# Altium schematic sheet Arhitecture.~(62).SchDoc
size A3; SheetNumber: 1; SheetTotal: 14
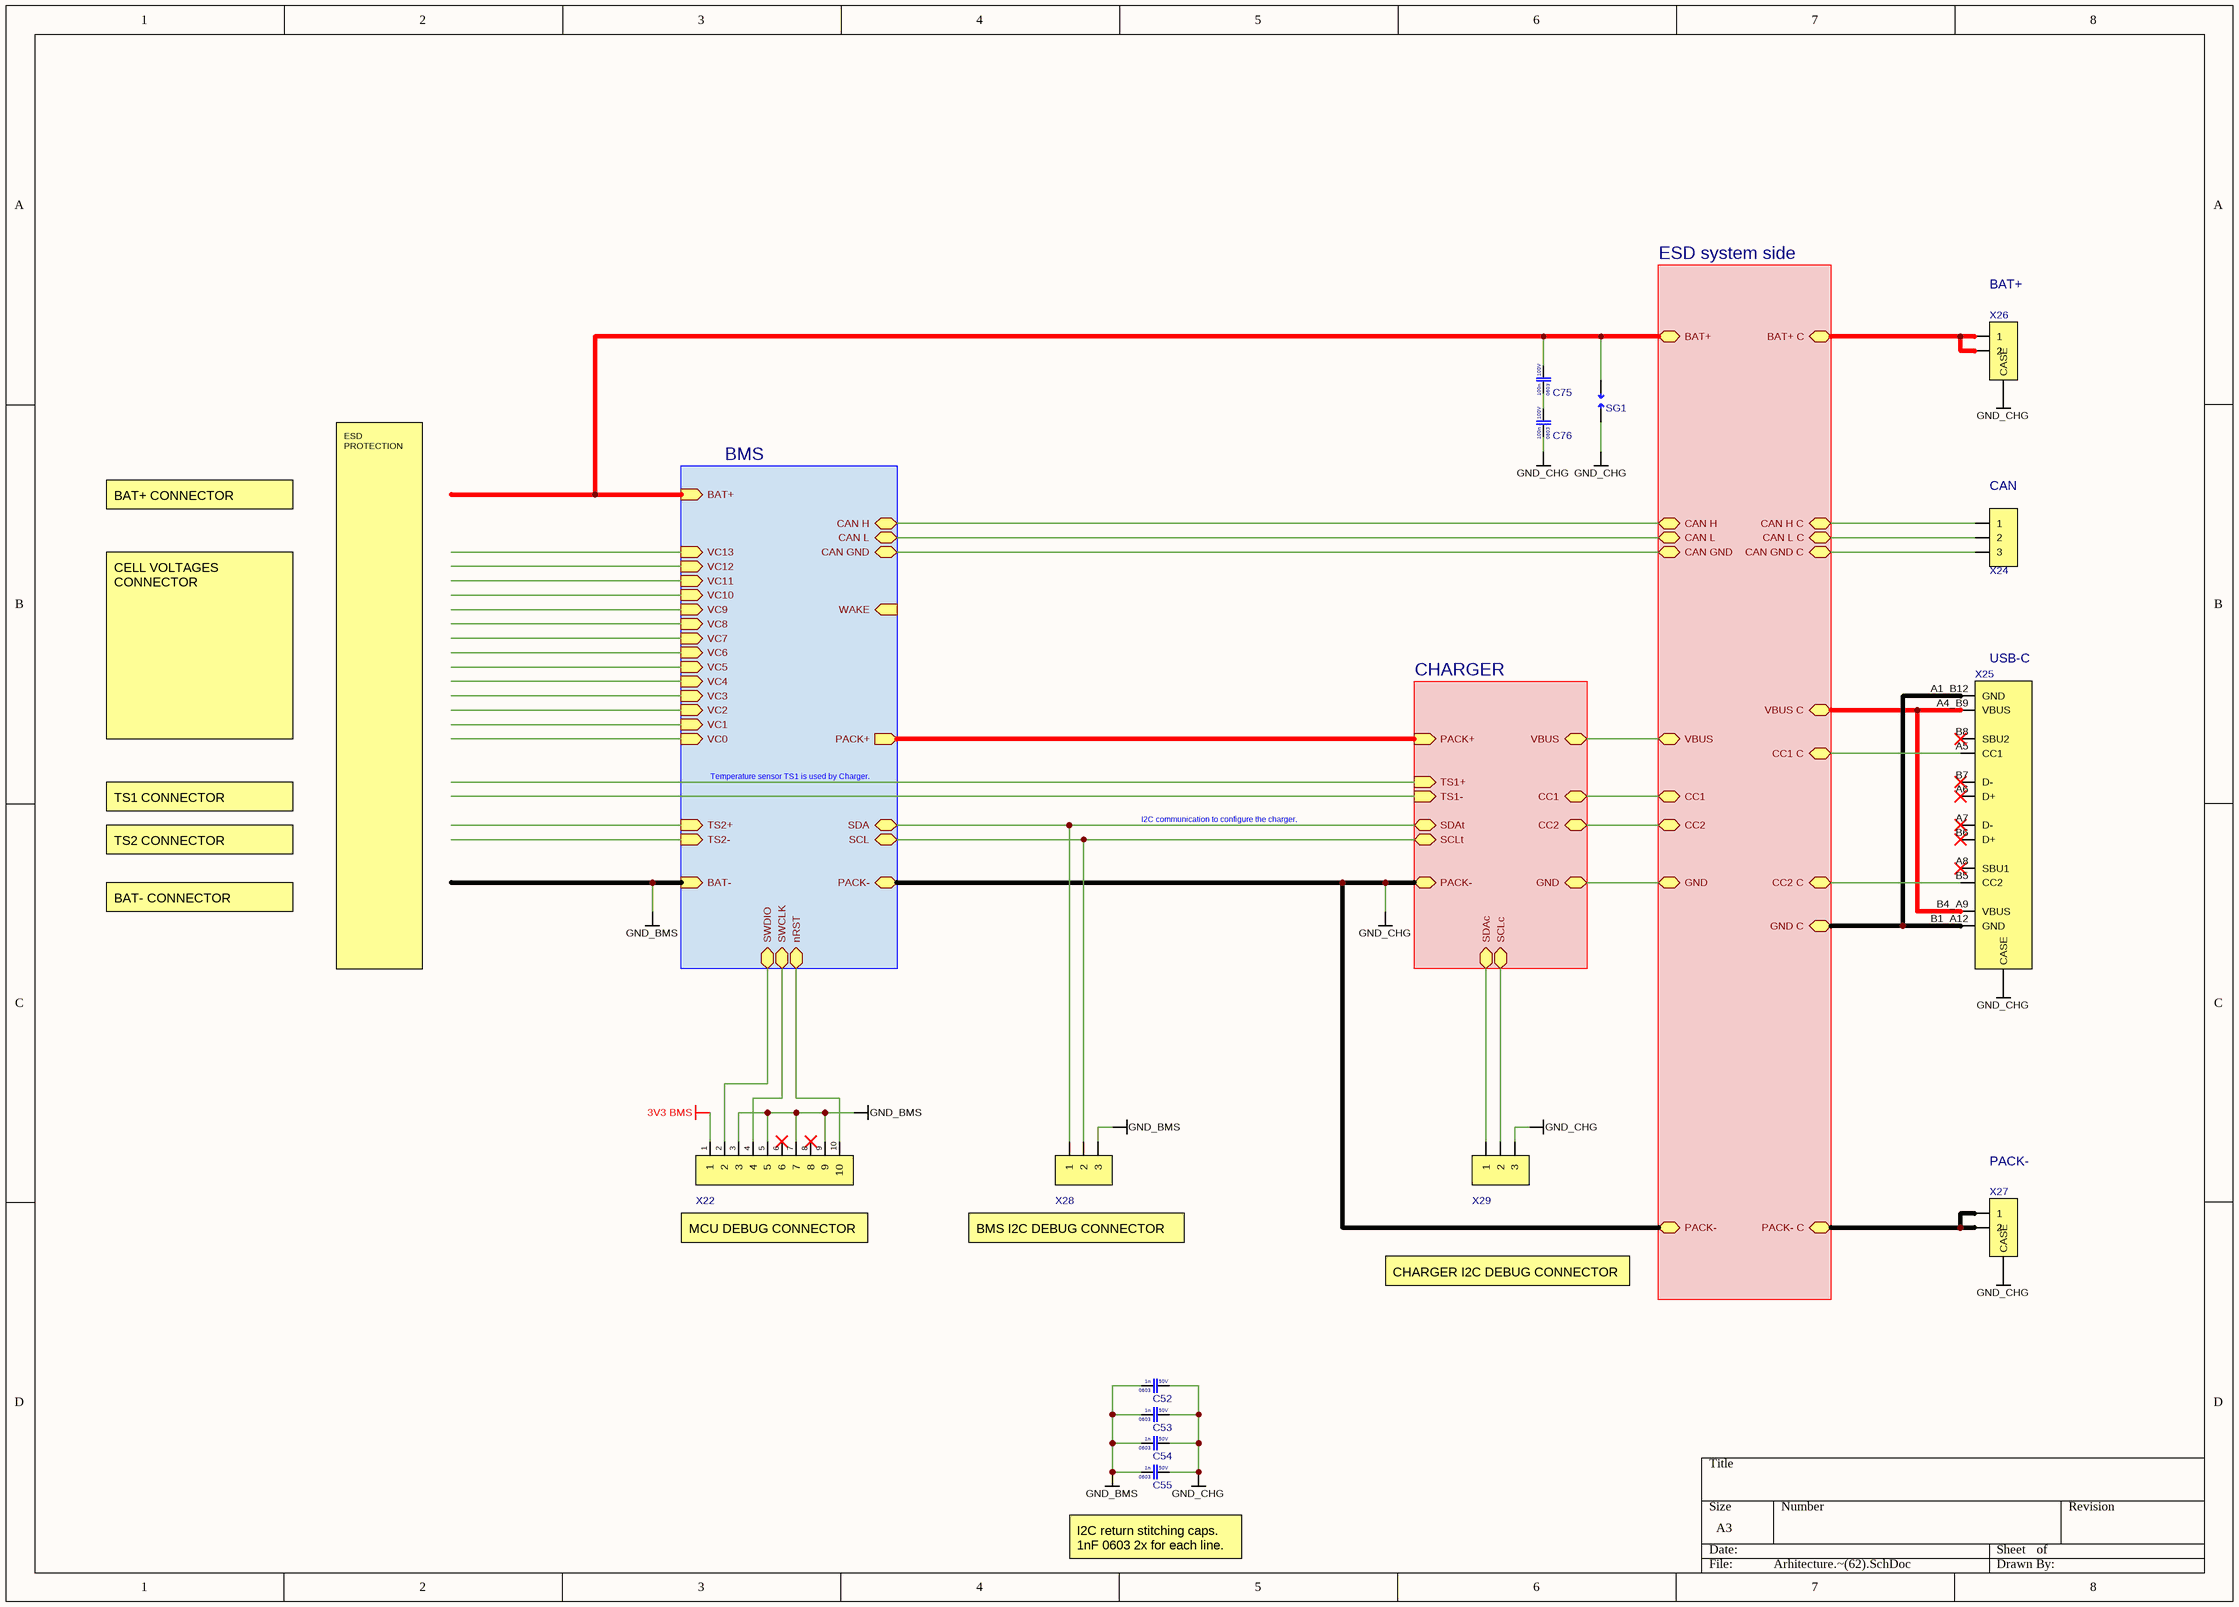
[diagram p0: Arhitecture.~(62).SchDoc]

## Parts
C52  Voltage Rating: 50V  Case Code (Imperial): 0603  Capacitance: 1n  [CAP 0603]  (hidden comment: CL10B102KB8NNNC)
C53  Voltage Rating: 50V  Case Code (Imperial): 0603  Capacitance: 1n  [CAP 0603]  (hidden comment: CL10B102KB8NNNC)
C54  Voltage Rating: 50V  Case Code (Imperial): 0603  Capacitance: 1n  [CAP 0603]  (hidden comment: CL10B102KB8NNNC)
C55  Voltage Rating: 50V  Case Code (Imperial): 0603  Capacitance: 1n  [CAP 0603]  (hidden comment: CL10B102KB8NNNC)
C75  Voltage Rating: 100V  Case Code (Imperial): 0603  Capacitance: 100n  [CAP 0603]  (hidden comment: CC0603KRX7R0BB104)
C76  Voltage Rating: 100V  Case Code (Imperial): 0603  Capacitance: 100n  [CAP 0603]  (hidden comment: CC0603KRX7R0BB104)
SG1  Spark gap  [Spark Gap 0.270mm]  (value not drawn)  (no BOM)
X22  HX IDC127-2-05-S-4.9  [JTAG Cortex connector]  (value not drawn)
X24  S3B-XH-A-1(LF)(SN)  [S3B-XH-A-1(LF)(SN)]  (value not drawn)
X25  USB-TYPE-C-018  [TYPE-C 16PIN 2MD]  (value not drawn)
X26  XT30PW-M30.G.Y  [XT30PW-M30.G.Y]  (value not drawn)
X27  XT30PW-M30.G.Y  [XT30PW-M30.G.Y]  (value not drawn)
X28  2.54-1*3PPin  [Pin header 1x3 2.54mmP THT Vertical]  (value not drawn)
X29  2.54-1*3PPin  [Pin header 1x3 2.54mmP THT Vertical]  (value not drawn)

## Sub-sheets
BMS = BMS.SchDoc: BAT+ (in), BAT- (in), VC0 (in), VC1 (in), VC2 (in), VC3 (in), VC4 (in), VC5 (in), VC6 (in), VC7 (in), VC8 (in), VC9 (in), VC10 (in), VC11 (in), VC12 (in), VC13 (in), PACK+ (out), PACK- (bidir), SCL (bidir), SDA (bidir), CAN H (bidir), CAN L (bidir), TS2+ (in), TS2- (in), WAKE (in), SWDIO (bidir), SWCLK (bidir), nRST (bidir), CAN GND (bidir)
CHARGER = CHARGER.SchDoc: PACK+ (in), PACK- (bidir), SDAt (bidir), SCLt (bidir), TS1+ (in), TS1- (in), SDAc (bidir), SCLc (bidir), CC1 (bidir), CC2 (bidir), GND (bidir), VBUS (bidir)
ESD system side = ESD system side.SchDoc: CAN H (bidir), CAN L (bidir), CAN GND (bidir), CAN H C (bidir), CAN L C (bidir), CAN GND C (bidir), VBUS C (bidir), GND C (bidir), CC1 C (bidir), CC2 C (bidir), VBUS (bidir), CC1 (bidir), CC2 (bidir), GND (bidir), BAT+ C (bidir), BAT+ (bidir), PACK- C (bidir), PACK- (bidir)

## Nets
3V3 BMS: X22.1
GND_BMS: C52.1 C53.1 C54.1 C55.1 X22.3 X22.5 X22.7 X22.9 X28.3 ; sheet BMS/BAT-
GND_CHG: C52.2 C53.2 C54.2 C55.2 C76.1 SG1.1 X25.CASE X26.CASE X27.CASE X29.3 ; sheet BMS/PACK-, sheet CHARGER/PACK-, sheet ESD system side/PACK-
NetC75_1: C75.1 C76.2
NetC75_2: C75.2 SG1.2 ; sheet BMS/BAT+, sheet ESD system side/BAT+
NetX22_2: X22.2 ; sheet BMS/SWDIO
NetX22_4: X22.4 ; sheet BMS/SWCLK
NetX22_10: X22.10 ; sheet BMS/nRST
NetX24_1: X24.1 ; sheet ESD system side/CAN H C
NetX24_2: X24.2 ; sheet ESD system side/CAN L C
NetX24_3: X24.3 ; sheet ESD system side/CAN GND C
NetX25_A1_B12: X25.A1_B12(GND) X25.B1_A12(GND) ; sheet ESD system side/GND C
NetX25_A4_B9: X25.A4_B9(VBUS) X25.B4_A9(VBUS) ; sheet ESD system side/VBUS C
NetX25_A5: X25.A5(CC1) ; sheet ESD system side/CC1 C
NetX25_B5: X25.B5(CC2) ; sheet ESD system side/CC2 C
NetX26_1: X26.1 X26.2 ; sheet ESD system side/BAT+ C
NetX27_1: X27.1 X27.2 ; sheet ESD system side/PACK- C
NetX28_1: X28.1 ; sheet BMS/SDA, sheet CHARGER/SDAt
NetX28_2: X28.2 ; sheet BMS/SCL, sheet CHARGER/SCLt
NetX29_1: X29.1 ; sheet CHARGER/SDAc
NetX29_2: X29.2 ; sheet CHARGER/SCLc
(unnamed): sheet BMS/PACK+, sheet CHARGER/PACK+
(unnamed): sheet BMS/CAN H, sheet ESD system side/CAN H  [a separate net that carries the same name]
(unnamed): sheet BMS/CAN L, sheet ESD system side/CAN L  [a separate net that carries the same name]
(unnamed): sheet BMS/CAN GND, sheet ESD system side/CAN GND  [a separate net that carries the same name]
(unnamed): sheet CHARGER/CC1, sheet ESD system side/CC1  [a separate net that carries the same name]
(unnamed): sheet CHARGER/CC2, sheet ESD system side/CC2  [a separate net that carries the same name]
(unnamed): sheet CHARGER/GND, sheet ESD system side/GND  [a separate net that carries the same name]
(unnamed): sheet CHARGER/VBUS, sheet ESD system side/VBUS  [a separate net that carries the same name]

Not connected (* = marked no-connect by the designer): X22 6* 8*; X25 A6(D+)* A7(D-)* A8(SBU1)* B6(D+)* B7(D-)* B8(SBU2)*

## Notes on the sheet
- (near X26) BAT+
- BAT+ CONNECTOR
- (near X24) CAN
- (near X25) USB-C
- CELL VOLTAGES CONNECTOR
- TS1 CONNECTOR
- Temperature sensor TS1 is used by Charger.
- I2C communication to configure the charger.
- BAT- CONNECTOR
- TS2 CONNECTOR
- ESD PROTECTION
- (near X27) PACK-
- MCU DEBUG CONNECTOR
- BMS I2C DEBUG CONNECTOR
- CHARGER I2C DEBUG CONNECTOR
- (near C55) I2C return stitching caps.
  1nF 0603 2x for each line.

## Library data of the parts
C52-C55 = CL10B102KB8NNNC: Cap 1nF 50V 0603 X7R; Manufacturer: Samsung
C75 C76 = CC0603KRX7R0BB104: Cap 100nF 100V 0603 X7R; Manufacturer: YAGEO
SG1 = Spark gap: Generic Spark gap symbol
X22 = HX IDC127-2-05-S-4.9: JTAG Cortex MCU Debug connector 2x5P 1.27mmP; Manufacturer: hanxia
X24 = S3B-XH-A-1(LF)(SN): JST XH 1x3 2.50mmP THT Right-angle
X25 = USB-TYPE-C-018: USB-C 16P Right-angle; Manufacturer: DEALON
X26 X27 = XT30PW-M30.G.Y: XT30 Male THT Right-angle; Manufacturer: Changzhou Amass Elec
X28 X29 = 2.54-1*3PPin: Pin header 1x3 2.54mmP THT Vertical; Manufacturer: BOOMELE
